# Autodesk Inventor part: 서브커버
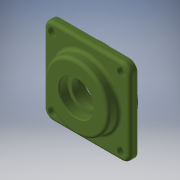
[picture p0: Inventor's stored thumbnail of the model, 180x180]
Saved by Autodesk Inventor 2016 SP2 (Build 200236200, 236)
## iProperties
Created: 2018-09
Part Number: 서브커버
Material: 알루미늄 6061
Document SubType Name: Modeling
Designer: mduedu
Density: 2.71 g/cm^3
Mass: 206.511 g
Surface Area: 197.007 cm^2
Volume: 76.2032 cm^3
Appearance: 올리브 녹색
Author: mduedu
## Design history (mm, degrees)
sketch "스케치1"
  geometry: L1 (-40, -40)-(40, -40); L2 (40, -40)-(40, 40); L3 (40, 40)-(-40, 40); L4 (-40, 40)-(-40, -40); L5 (-40, -40)-(40, 40); L6 (40, -40)-(-40, 40); 1 further point
  constraints: 12 end point, 2 midpoint, 2 parallel, 1 horizontal, 1 perpendicular
  dimensions: "d0" = 80 distance of L3.end L2.end; "d1" = 80 distance of L2.end L1.end
extrude "돌출1" new body sketch "스케치1" distance "d2" = 7; taper "d3" = 0 deg
sketch "스케치2"
  geometry: C1 r 30 at (0, 0); 1 further point
  constraints: 1 centre point, 1 coincident
  dimensions: "d4" = 60 diameter of C1
extrude "돌출2" join sketch "스케치2" distance "d5" = 10; taper "d6" = 0 deg
sketch "스케치3"
  geometry: C1 r 32.5 at (0, 0); 1 further point
  constraints: 1 centre point, 1 coincident
  dimensions: "d7" = 65 diameter of C1
extrude "돌출3" join sketch "스케치3" distance "d8" = 9; taper "d9" = 0 deg
sketch "스케치4"
  geometry: L1 (-32.5, -9)-(32.5, -9) reference; L2 (30, 17)-(-30, 17) reference; L3 (0, 17)-(0, -9); L4 (0, -9)-(20, -9); L5 (20, -9)-(20, 3); L6 (20, 3)-(0, 3); L7 (0, 3)-(0, -9); L8 (0, 3)-(12.5, 3); L9 (12.5, 3)-(12.5, 8.7); L10 (12.5, 8.7)-(0, 8.7); L11 (0, 8.7)-(0, 3); L12 (0, 8.7)-(16, 8.7); L13 (16, 8.7)-(16, 17); L14 (16, 17)-(0, 17); L15 (0, 17)-(0, 8.7); 1 further point
  constraints: 26 end point, 6 parallel, 3 horizontal, 3 perpendicular, 2 midpoint, 1 point on line
  dimensions: "d10" = 12 distance of L4.end L5.end; "d12" = 8.3 distance of L12.end L13.end; "d13" = 32 diameter of L13 L3; "d14" = 25 diameter of L9 L3; "d15" = 40 diameter of L5 L3
revolve "회전1" sketch "스케치4" stored, may be unused: angle "d16" = 90 deg
fillet "모깎기1" dims "d17" = 8
fillet "모깎기2" dims "d18" = 3
fillet "모깎기3" dims "d19" = 3
chamfer "모따기1" distance "d20" = 0.8; stored, may be unused: second distance "d21" = 2, angle "d22" = 30 deg
chamfer "모따기2" distance "d23" = 1; stored, may be unused: second distance "d24" = 2, angle "d25" = 30 deg
fillet "모깎기4" dims "d26" = 0.3
sketch "스케치5"
  geometry: A1 r 8 centre (-32, 32) between (-32, 40) and (-40, 32) reference; A2 r 8 centre (-32, -32) between (-40, -32) and (-32, -40) reference; A3 r 8 centre (32, -32) between (32, -40) and (40, -32) reference; A4 r 8 centre (32, 32) between (40, 32) and (32, 40) reference; 5 further points
  constraints: 4 coincident
hole "구멍1" sketch "스케치5" at (-32, 32), (32, 32), (32, -32), (-32, -32) diameter "d27" = 4.5; stored, may be unused: countersink angle "d31" = 90 deg, drill point angle "d33" = 118 deg; dims "d28" = 6, "d29" = 8, "d30" = 4.4, "d32" = 8
node "솔리드1"
